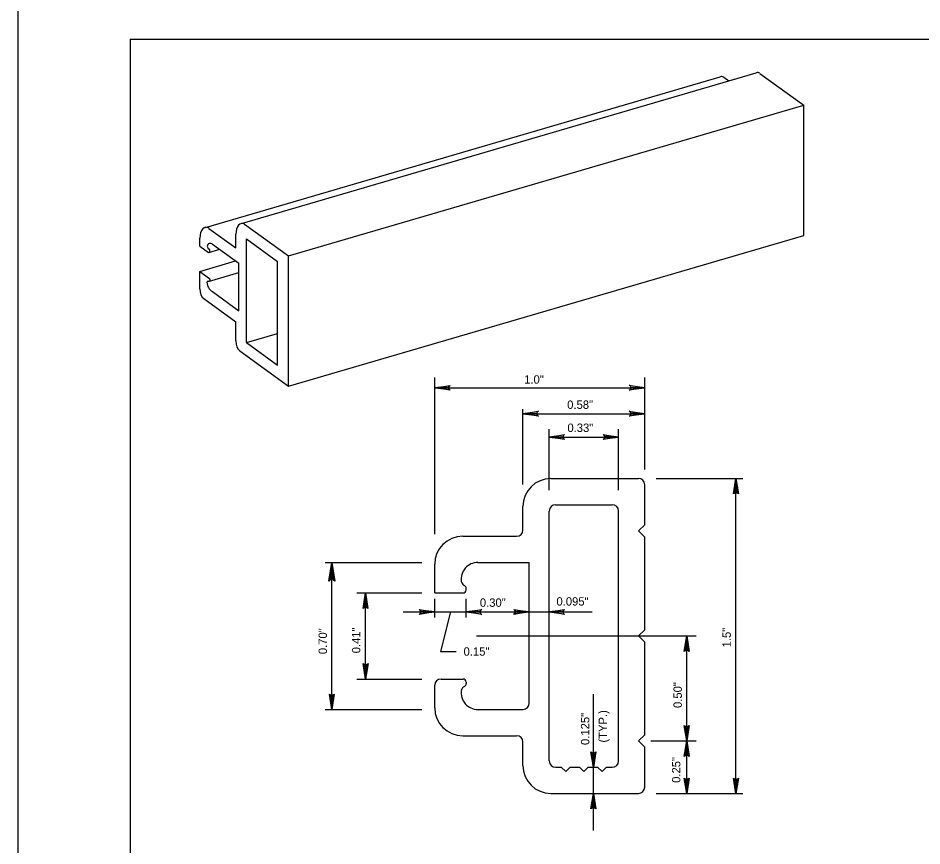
# Model space of a CAD drawing. Extents: x 650495 to 652241, y 298458 to 299646.
# Drawn here: x 650495.3 to 650818, y 298748.5 to 299044.1 of the extents above; entities that cross this region are included whole.
import ezdxf

# ---------------------------------------------------------------- set-up
doc = ezdxf.new("R2010")
doc.units = 0
for name, color, linetype in [('1', 7, 'Continuous'), ('2', 7, 'Continuous'), ('PLT-BNDY', 7, 'Continuous')]:
    doc.layers.add(name, color=color, linetype=linetype)

msp = doc.modelspace()

# ---------------------------------------------------------------- linework, layer by layer
at = {"layer": '1'}
for q in [(651321.31, 299036.63), (650535.31, 298472.63)]:
    msp.add_line((650535.31, 299036.63), q, dxfattribs=at)
at = {"layer": '2'}
for p, q in [((650575.03, 298970.77), (650758.88, 299024.56)), ((650562.19, 298969.37), (650745.99, 299023.15)), ((650747.31, 299022.97), (650749.08, 299021.69)), ((650760.18, 299024.39), (650775.84, 299013.04)), ((650591.84, 298959.2), (650775.84, 299013.04)), ((650775.84, 298966.51), (650775.84, 299013.04)), ((650576.15, 298970.57), (650591.84, 298959.2)), ((650563.48, 298969.01), (650573.07, 298962.06)), ((650573.07, 298962.06), (650573.07, 298966.98)), ((650591.84, 298912.67), (650775.84, 298966.51)), ((650560.2, 298962.65), (650560.2, 298965.56)), ((650564.72, 298963.36), (650574.13, 298956.54)), ((650576.91, 298965.26), (650587.99, 298957.23)), ((650576.91, 298928.24), (650576.91, 298965.26)), ((650560.2, 298962.65), (650563.3, 298960.4)), ((650563.55, 298960.46), (650567.23, 298961.54)), ((650563.82, 298960.92), (650563.82, 298961.14)), ((650560.2, 298953.67), (650572.94, 298957.4)), ((650587.99, 298920.21), (650587.99, 298957.23)), ((650591.84, 298912.67), (650591.84, 298959.2)), ((650560.2, 298953.67), (650563.71, 298951.12)), ((650560.2, 298947.48), (650560.2, 298953.67)), ((650574.13, 298939.59), (650574.13, 298956.54)), ((650563.63, 298950.14), (650574.13, 298953.21)), ((650561.59, 298943.93), (650573.07, 298935.61)), ((650564.7, 298946.42), (650574.13, 298939.59)), ((650573.07, 298928.83), (650573.07, 298935.61)), ((650576.91, 298928.24), (650587.99, 298931.48)), ((650576.91, 298928.24), (650587.99, 298920.21)), ((650574.45, 298925.27), (650591.84, 298912.67)), ((650644.08, 298859.79), (650644.08, 298915.76)), ((650719.07, 298882.92), (650719.07, 298915.76)), ((650644.08, 298912.08), (650719.07, 298912.08)), ((650675.58, 298877.58), (650675.58, 298904.5)), ((650675.58, 298902.83), (650719.07, 298902.83)), ((650684.95, 298875.52), (650684.95, 298897.26)), ((650709.7, 298875.52), (650709.7, 298897.26)), ((650684.95, 298894.5), (650709.7, 298894.5)), ((650685.58, 298879.7), (650716.82, 298879.7)), ((650723.11, 298879.7), (650754.1, 298879.7)), ((650751.61, 298767.21), (650751.61, 298879.7)), ((650719.07, 298863.2), (650719.07, 298877.45)), ((650675.58, 298861.33), (650675.58, 298869.7)), ((650687.2, 298870.33), (650707.45, 298870.33)), ((650684.95, 298778.83), (650684.95, 298868.08)), ((650709.7, 298778.83), (650709.7, 298868.08)), ((650716.82, 298860.95), (650719.07, 298863.2)), ((650716.82, 298860.95), (650719.07, 298858.7)), ((650654.08, 298859.08), (650673.33, 298859.08)), ((650719.07, 298825.7), (650719.07, 298858.7)), ((650604.97, 298849.7), (650639.52, 298849.7)), ((650607.34, 298797.2), (650607.34, 298849.7)), ((650644.08, 298838.83), (650644.08, 298849.08)), ((650659.5, 298849.7), (650677.83, 298849.7)), ((650677.83, 298799.45), (650677.83, 298849.7)), ((650616.3, 298838.83), (650639.52, 298838.83)), ((650619.37, 298808.08), (650619.37, 298838.83)), ((650644.08, 298838.83), (650654.21, 298838.83)), ((650655.33, 298839.95), (650655.33, 298840.43)), ((650644.08, 298830), (650644.08, 298836.71)), ((650655.33, 298830), (650655.33, 298836.71)), ((650632.82, 298832.06), (650644.08, 298832.06)), ((650644.08, 298832.06), (650655.33, 298832.06)), ((650649.7, 298832.06), (650646.18, 298817.91)), ((650655.33, 298832.06), (650677.83, 298832.06)), ((650677.83, 298832.06), (650684.95, 298832.06)), ((650684.95, 298832.06), (650700.33, 298832.06)), ((650716.82, 298823.45), (650719.07, 298825.7)), ((650658.95, 298823.45), (650737.45, 298823.45)), ((650716.82, 298823.45), (650719.07, 298821.2)), ((650719.07, 298788.2), (650719.07, 298821.2)), ((650730.98, 298823.45), (650737.45, 298823.45)), ((650734.04, 298785.95), (650734.04, 298823.45)), ((650646.18, 298817.91), (650651.74, 298817.91)), ((650616.3, 298808.08), (650639.52, 298808.08)), ((650644.08, 298797.83), (650644.08, 298805.83)), ((650646.33, 298808.08), (650654.21, 298808.08)), ((650655.33, 298806.95), (650655.33, 298806.48)), ((650700.73, 298776.58), (650700.73, 298802.7)), ((650604.97, 298797.2), (650639.52, 298797.2)), ((650659.5, 298797.2), (650675.58, 298797.2)), ((650654.08, 298787.83), (650673.33, 298787.83)), ((650716.82, 298785.95), (650719.07, 298788.2)), ((650716.82, 298785.95), (650719.07, 298783.7)), ((650721.26, 298785.95), (650737.45, 298785.95)), ((650734.04, 298767.21), (650734.04, 298785.95)), ((650675.58, 298777.21), (650675.58, 298785.58)), ((650719.07, 298769.46), (650719.07, 298783.7)), ((650687.2, 298776.58), (650689.28, 298776.58)), ((650690.84, 298775.02), (650689.28, 298776.58)), ((650690.84, 298775.02), (650692.41, 298776.58)), ((650692.41, 298776.58), (650695.76, 298776.58)), ((650697.32, 298775.02), (650695.76, 298776.58)), ((650697.32, 298775.02), (650698.89, 298776.58)), ((650698.89, 298776.58), (650702.24, 298776.58)), ((650700.73, 298767.21), (650700.73, 298776.58)), ((650703.81, 298775.02), (650702.24, 298776.58)), ((650703.81, 298775.02), (650705.37, 298776.58)), ((650705.37, 298776.58), (650707.45, 298776.58)), ((650685.58, 298767.21), (650716.82, 298767.21)), ((650700.73, 298754.04), (650700.73, 298767.21)), ((650723.11, 298767.21), (650754.1, 298767.21))]:
    msp.add_line(p, q, dxfattribs=at)
for points in [[(650649.33, 298911.42), (650649.14, 298911.8), (650644.08, 298912.08), (650649.33, 298911.42), (650649.6, 298911.19), (650644.08, 298912.08), (650649.13, 298912.33), (650649.32, 298912.71), (650644.08, 298912.08), (650649.6, 298912.96), (650649.32, 298912.71)], [(650713.82, 298912.74), (650714.01, 298912.36), (650719.07, 298912.08), (650713.82, 298912.74), (650713.55, 298912.97), (650719.07, 298912.08), (650714.02, 298911.83), (650713.83, 298911.45), (650719.07, 298912.08), (650713.55, 298911.2), (650713.83, 298911.45)], [(650680.83, 298902.17), (650680.63, 298902.55), (650675.58, 298902.83), (650680.83, 298902.17), (650681.1, 298901.94), (650675.58, 298902.83), (650680.63, 298903.08), (650680.82, 298903.46), (650675.58, 298902.83), (650681.1, 298903.71), (650680.82, 298903.46)], [(650713.82, 298903.49), (650714.01, 298903.11), (650719.07, 298902.83), (650713.82, 298903.49), (650713.55, 298903.72), (650719.07, 298902.83), (650714.02, 298902.58), (650713.83, 298902.2), (650719.07, 298902.83), (650713.55, 298901.95), (650713.83, 298902.2)], [(650690.21, 298893.84), (650690.01, 298894.22), (650684.95, 298894.5), (650690.21, 298893.84), (650690.47, 298893.61), (650684.95, 298894.5), (650690.01, 298894.75), (650690.19, 298895.13), (650684.95, 298894.5), (650690.47, 298895.38), (650690.19, 298895.13)], [(650704.44, 298895.16), (650704.64, 298894.78), (650709.7, 298894.5), (650704.44, 298895.16), (650704.18, 298895.39), (650709.7, 298894.5), (650704.64, 298894.25), (650704.46, 298893.88), (650709.7, 298894.5), (650704.18, 298893.63), (650704.46, 298893.88)], [(650750.95, 298874.45), (650751.34, 298874.64), (650751.61, 298879.7), (650750.95, 298874.45), (650750.72, 298874.18), (650751.61, 298879.7), (650751.86, 298874.65), (650752.24, 298874.46), (650751.61, 298879.7), (650752.49, 298874.18), (650752.24, 298874.46)], [(650606.55, 298843.4), (650607.01, 298843.63), (650607.34, 298849.7), (650606.55, 298843.4), (650606.27, 298843.07), (650607.34, 298849.7), (650607.64, 298843.64), (650608.09, 298843.41), (650607.34, 298849.7), (650608.39, 298843.07), (650608.09, 298843.41)], [(650606.55, 298843.4), (650607.01, 298843.63), (650607.34, 298849.7), (650606.55, 298843.4), (650606.27, 298843.07), (650607.34, 298849.7), (650607.64, 298843.64), (650608.09, 298843.41), (650607.34, 298849.7), (650608.39, 298843.07), (650608.09, 298843.41)], [(650618.71, 298833.57), (650619.09, 298833.77), (650619.37, 298838.83), (650618.71, 298833.57), (650618.48, 298833.3), (650619.37, 298838.83), (650619.62, 298833.77), (650619.99, 298833.59), (650619.37, 298838.83), (650620.24, 298833.3), (650619.99, 298833.59)], [(650638.82, 298832.72), (650639.02, 298832.34), (650644.08, 298832.06), (650638.82, 298832.72), (650638.55, 298832.95), (650644.08, 298832.06), (650639.02, 298831.81), (650638.84, 298831.43), (650644.08, 298832.06), (650638.55, 298831.18), (650638.84, 298831.43)], [(650660.59, 298831.4), (650660.39, 298831.78), (650655.33, 298832.06), (650660.59, 298831.4), (650660.86, 298831.17), (650655.33, 298832.06), (650660.39, 298832.31), (650660.57, 298832.68), (650655.33, 298832.06), (650660.86, 298832.93), (650660.57, 298832.68)], [(650672.58, 298832.72), (650672.77, 298832.34), (650677.83, 298832.06), (650672.58, 298832.72), (650672.31, 298832.95), (650677.83, 298832.06), (650672.78, 298831.81), (650672.59, 298831.43), (650677.83, 298832.06), (650672.31, 298831.18), (650672.59, 298831.43)], [(650690.21, 298831.4), (650690.01, 298831.78), (650684.95, 298832.06), (650690.21, 298831.4), (650690.47, 298831.17), (650684.95, 298832.06), (650690.01, 298832.31), (650690.19, 298832.68), (650684.95, 298832.06), (650690.47, 298832.93), (650690.19, 298832.68)], [(650733.38, 298818.2), (650733.76, 298818.39), (650734.04, 298823.45), (650733.38, 298818.2), (650733.15, 298817.93), (650734.04, 298823.45), (650734.29, 298818.4), (650734.66, 298818.21), (650734.04, 298823.45), (650734.91, 298817.93), (650734.66, 298818.21)], [(650620.03, 298813.33), (650619.65, 298813.14), (650619.37, 298808.08), (650620.03, 298813.33), (650620.26, 298813.6), (650619.37, 298808.08), (650619.12, 298813.13), (650618.74, 298813.32), (650619.37, 298808.08), (650618.49, 298813.6), (650618.74, 298813.32)], [(650608, 298802.46), (650607.62, 298802.26), (650607.34, 298797.2), (650608, 298802.46), (650608.23, 298802.73), (650607.34, 298797.2), (650607.09, 298802.26), (650606.71, 298802.44), (650607.34, 298797.2), (650606.46, 298802.73), (650606.71, 298802.44)], [(650734.7, 298791.21), (650734.32, 298791.01), (650734.04, 298785.95), (650734.7, 298791.21), (650734.93, 298791.48), (650734.04, 298785.95), (650733.79, 298791.01), (650733.41, 298791.19), (650734.04, 298785.95), (650733.16, 298791.48), (650733.41, 298791.19)], [(650733.38, 298780.7), (650733.76, 298780.9), (650734.04, 298785.95), (650733.38, 298780.7), (650733.15, 298780.43), (650734.04, 298785.95), (650734.29, 298780.9), (650734.66, 298780.72), (650734.04, 298785.95), (650734.91, 298780.43), (650734.66, 298780.72)], [(650701.39, 298781.83), (650701.01, 298781.64), (650700.73, 298776.58), (650701.39, 298781.83), (650701.62, 298782.1), (650700.73, 298776.58), (650700.48, 298781.64), (650700.11, 298781.82), (650700.73, 298776.58), (650699.85, 298782.1), (650700.11, 298781.82)], [(650734.7, 298772.46), (650734.32, 298772.26), (650734.04, 298767.21), (650734.7, 298772.46), (650734.93, 298772.73), (650734.04, 298767.21), (650733.79, 298772.26), (650733.41, 298772.45), (650734.04, 298767.21), (650733.16, 298772.73), (650733.41, 298772.45)], [(650752.27, 298772.46), (650751.89, 298772.26), (650751.61, 298767.21), (650752.27, 298772.46), (650752.5, 298772.73), (650751.61, 298767.21), (650751.36, 298772.26), (650750.99, 298772.45), (650751.61, 298767.21), (650750.74, 298772.73), (650750.99, 298772.45)], [(650700.07, 298761.95), (650700.45, 298762.15), (650700.73, 298767.21), (650700.07, 298761.95), (650699.84, 298761.68), (650700.73, 298767.21), (650700.98, 298762.15), (650701.36, 298761.97), (650700.73, 298767.21), (650701.61, 298761.68), (650701.36, 298761.97)]]:
    msp.add_lwpolyline(points, dxfattribs=at)
for centre, radius, start, end in [((650563.95, 298962.6), 1.08, 44.621, 246.0481), ((650563.3, 298960.92), 0.52, 270, 0), ((650563.3, 298961.14), 0.52, 0, 66.0481), ((650563.38, 298950.65), 0.571, 250.8042, 54.059), ((650563.09, 298949.8), 0.333, 70.8042, 182.3162), ((650566.88, 298949.94), 4.13, 182.245, 238.3169), ((650685.58, 298869.7), 10, 90, 180), ((650716.82, 298877.45), 2.25, 0, 90), ((650687.2, 298868.08), 2.25, 90, 180), ((650707.45, 298868.08), 2.25, 0, 90), ((650673.33, 298861.33), 2.25, 270, 0), ((650654.08, 298849.08), 10, 90, 180), ((650659.5, 298843.7), 6, 90, 188.0391), ((650655.44, 298843.2), 1.91, 190.1449, 246.0481), ((650654.21, 298840.43), 1.12, 0, 66.0481), ((650654.21, 298839.95), 1.12, 270, 0), ((650646.33, 298805.83), 2.25, 90, 180), ((650655.44, 298803.71), 1.91, 113.9519, 169.8551), ((650654.21, 298806.95), 1.12, 0, 90), ((650654.21, 298806.48), 1.12, 293.9519, 360), ((650659.5, 298803.2), 6, 171.9609, 270), ((650675.58, 298799.45), 2.25, 270, 0), ((650654.08, 298797.83), 10, 180, 270), ((650673.33, 298785.58), 2.25, 0, 90), ((650685.58, 298777.21), 10, 180, 270), ((650687.2, 298778.83), 2.25, 180, 270), ((650707.45, 298778.83), 2.25, 270, 360), ((650716.82, 298769.46), 2.25, 270, 360)]:
    msp.add_arc(centre, radius, start, end, dxfattribs=at)
for centre, major_axis, start_param, end_param in [((650759.52, 299020.44), (0.26, -4.2), 2.759334, 3.301342), ((650746.64, 299019.03), (0.26, -4.2), 2.759334, 3.301342), ((650562.63, 298965.2), (0.26, -4.2), 2.674345, 4.589197), ((650575.49, 298966.61), (0.26, -4.2), 2.759334, 4.589197), ((650562.63, 298947.85), (0.26, 4.2), 1.693988, 2.807682), ((650575.5, 298929.19), (0.26, 4.2), 1.693988, 2.807682)]:
    msp.add_ellipse(centre, major_axis=major_axis, ratio=0.576402, start_param=start_param, end_param=end_param, dxfattribs=at)
at = {"layer": 'PLT-BNDY'}
msp.add_lwpolyline([(650495.31, 299051.63), (651336.31, 299051.63), (651336.31, 298457.63), (650495.31, 298457.63)], close=True, dxfattribs=at)

# ---------------------------------------------------------------- texts
at = {"layer": '2'}
for s, p in [('1.0"', (650676.01, 298913.56)), ('0.58"', (650691.37, 298904.56)), ('0.33"', (650691.45, 298896.31)), ('0.095"', (650687.54, 298834.3)), ('0.30"', (650660.19, 298833.87)), ('0.15"', (650654.37, 298816.41))]:
    msp.add_text(s, height=3, dxfattribs=at).set_placement(p)
for s, p in [('0.70"', (650605.61, 298816.96)), ('0.41"', (650617.52, 298817.27)), ('1.5"', (650749.8, 298819.39)), ('0.50"', (650732.31, 298797.74)), ('0.125"', (650699.28, 298784.52)), ('(TYP.)', (650705.61, 298785.38)), ('0.25"', (650731.79, 298770.99))]:
    msp.add_text(s, height=3, rotation=90, dxfattribs=at).set_placement(p)

doc.saveas('drawing.dxf')
